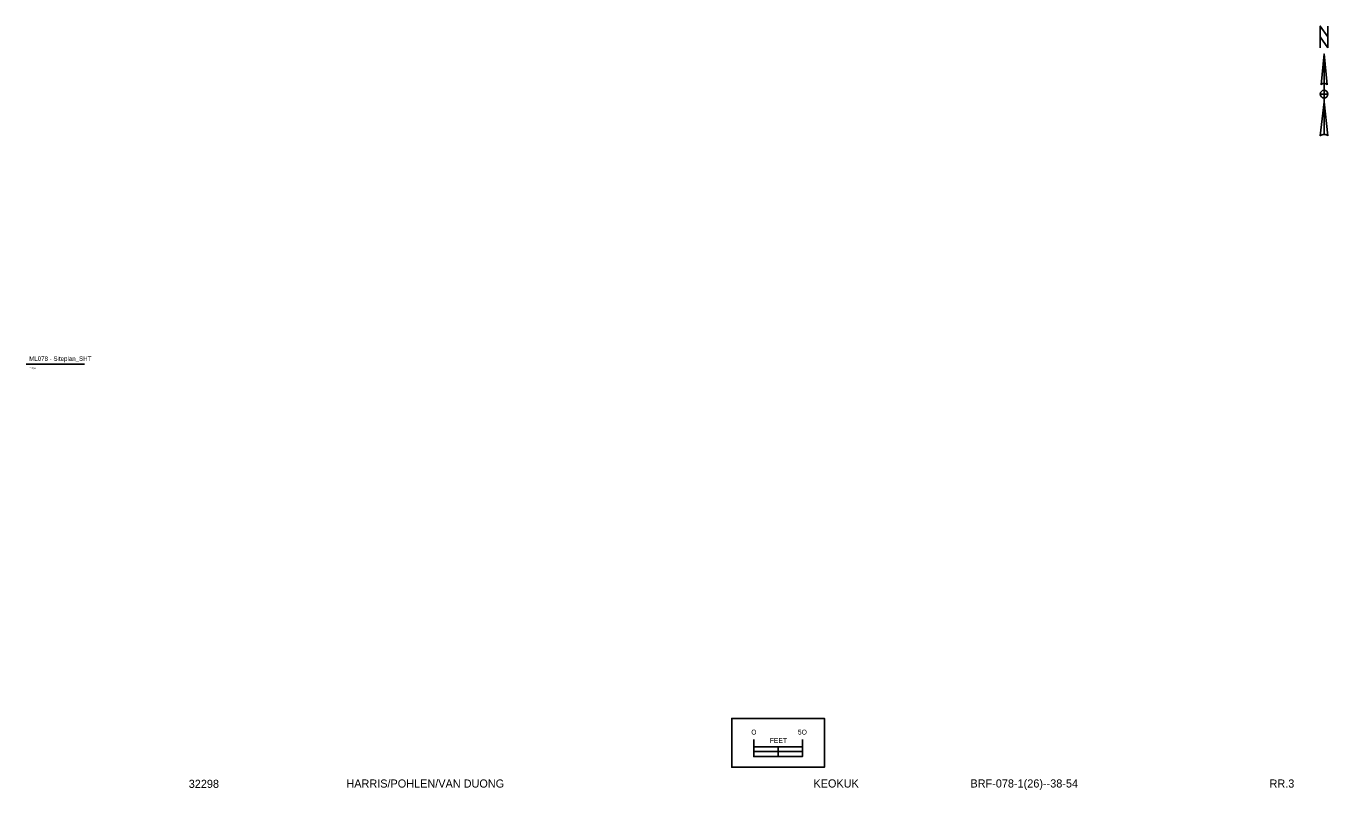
# Model space of a CAD drawing. Extents: x -0.12 to 2.54, y 0.07 to 1.64.
import ezdxf

# ---------------------------------------------------------------- set-up
doc = ezdxf.new("R2010")
doc.units = 0
doc.layers.add('Cell', color=7, linetype='Continuous')
doc.layers.add('SheetText', color=7, linetype='Continuous')

msp = doc.modelspace()

# ---------------------------------------------------------------- linework, layer by layer
at = {"layer": 'Cell'}
for p, q in [((2.5354, 1.5815), (2.5417, 1.5181)), ((2.5354, 1.5815), (2.5354, 1.4167)), ((2.5291, 1.5181), (2.5291, 1.5181)), ((2.5293, 1.5187), (2.5305, 1.52)), ((2.5275, 1.4136), (2.5354, 1.4833)), ((2.5354, 1.4912), (2.5354, 1.4912))]:
    msp.add_line(p, q, dxfattribs=at)
msp.add_lwpolyline([(2.5433, 1.5942), (2.5275, 1.6164), (2.5275, 1.6386), (2.5433, 1.6164)], close=True, dxfattribs=at)
for points in [[(2.5275, 1.5942), (2.5275, 1.6386), (2.5433, 1.6164), (2.5433, 1.6386)], [(2.5291, 1.5181), (2.5354, 1.5815), (2.5354, 1.5213)], [(2.5354, 1.4912), (2.5354, 1.4991), (2.5275, 1.4991)], [(2.5433, 1.4991), (2.5354, 1.4991), (2.5354, 1.507)], [(2.5354, 1.4167), (2.5354, 1.4833), (2.5433, 1.4136)]]:
    msp.add_lwpolyline(points, dxfattribs=at)
for centre, radius, start, end in [((2.5354, 1.5134), 0.00792, 90.0204, 143.1257), ((2.5354, 1.5134), 0.00792, 36.8481, 90.0218), ((2.5354, 1.4991), 0.00792, 90, 180), ((2.5354, 1.4991), 0.00792, 180, 270), ((2.5354, 1.4991), 0.00792, 0, 90), ((2.5354, 1.4991), 0.00792, 270, 360), ((2.5354, 1.4052), 0.0115, 89.9894, 133.619), ((2.5354, 1.4052), 0.0115, 46.4021, 90.0006)]:
    msp.add_arc(centre, radius, start, end, dxfattribs=at)
at = {"layer": 'SheetText'}
for p, q in [((-0.1242, 0.946), (-0.0047, 0.946)), ((1.4167, 0.142), (1.4167, 0.162)), ((1.4167, 0.142), (1.4167, 0.162))]:
    msp.add_line(p, q, dxfattribs=at)
for points in [[(1.3217, 0.22), (1.5117, 0.22), (1.5117, 0.12), (1.3217, 0.12)], [(1.3217, 0.22), (1.5117, 0.22), (1.5117, 0.12), (1.3217, 0.12)], [(1.3217, 0.12), (1.3217, 0.22), (1.5117, 0.22), (1.5117, 0.12)], [(1.4167, 0.1521), (1.4667, 0.1521), (1.4667, 0.162), (1.4167, 0.162)], [(1.3667, 0.142), (1.4167, 0.142), (1.4167, 0.1521), (1.3667, 0.1521)]]:
    msp.add_lwpolyline(points, close=True, dxfattribs=at)
for points in [[(1.3667, 0.177), (1.3667, 0.142), (1.4667, 0.142), (1.4667, 0.177)], [(1.3667, 0.162), (1.4667, 0.162)]]:
    msp.add_lwpolyline(points, dxfattribs=at)

# ---------------------------------------------------------------- texts
for s, height, p in [('ML078 - Siteplan_SHT', 0.009115, (-0.1177, 0.9526)), ('1"=50\'', 0.00391, (-0.1177, 0.9356)), ('O', 0.01, (1.3617, 0.187)), ('5O', 0.01, (1.4573, 0.187)), ('FEET', 0.01, (1.3997, 0.17)), ('32298', 0.01667, (0.2092, 0.0777)), ('HARRIS/POHLEN/VAN DUONG', 0.016667, (0.5322, 0.0783)), ('KEOKUK', 0.01667, (1.4891, 0.0785)), ('BRF-078-1(26)--38-54', 0.016667, (1.8108, 0.0785)), ('RR.3', 0.01667, (2.4236, 0.0783))]:
    msp.add_text(s, height=height, dxfattribs=at).set_placement(p)

doc.saveas('drawing.dxf')
